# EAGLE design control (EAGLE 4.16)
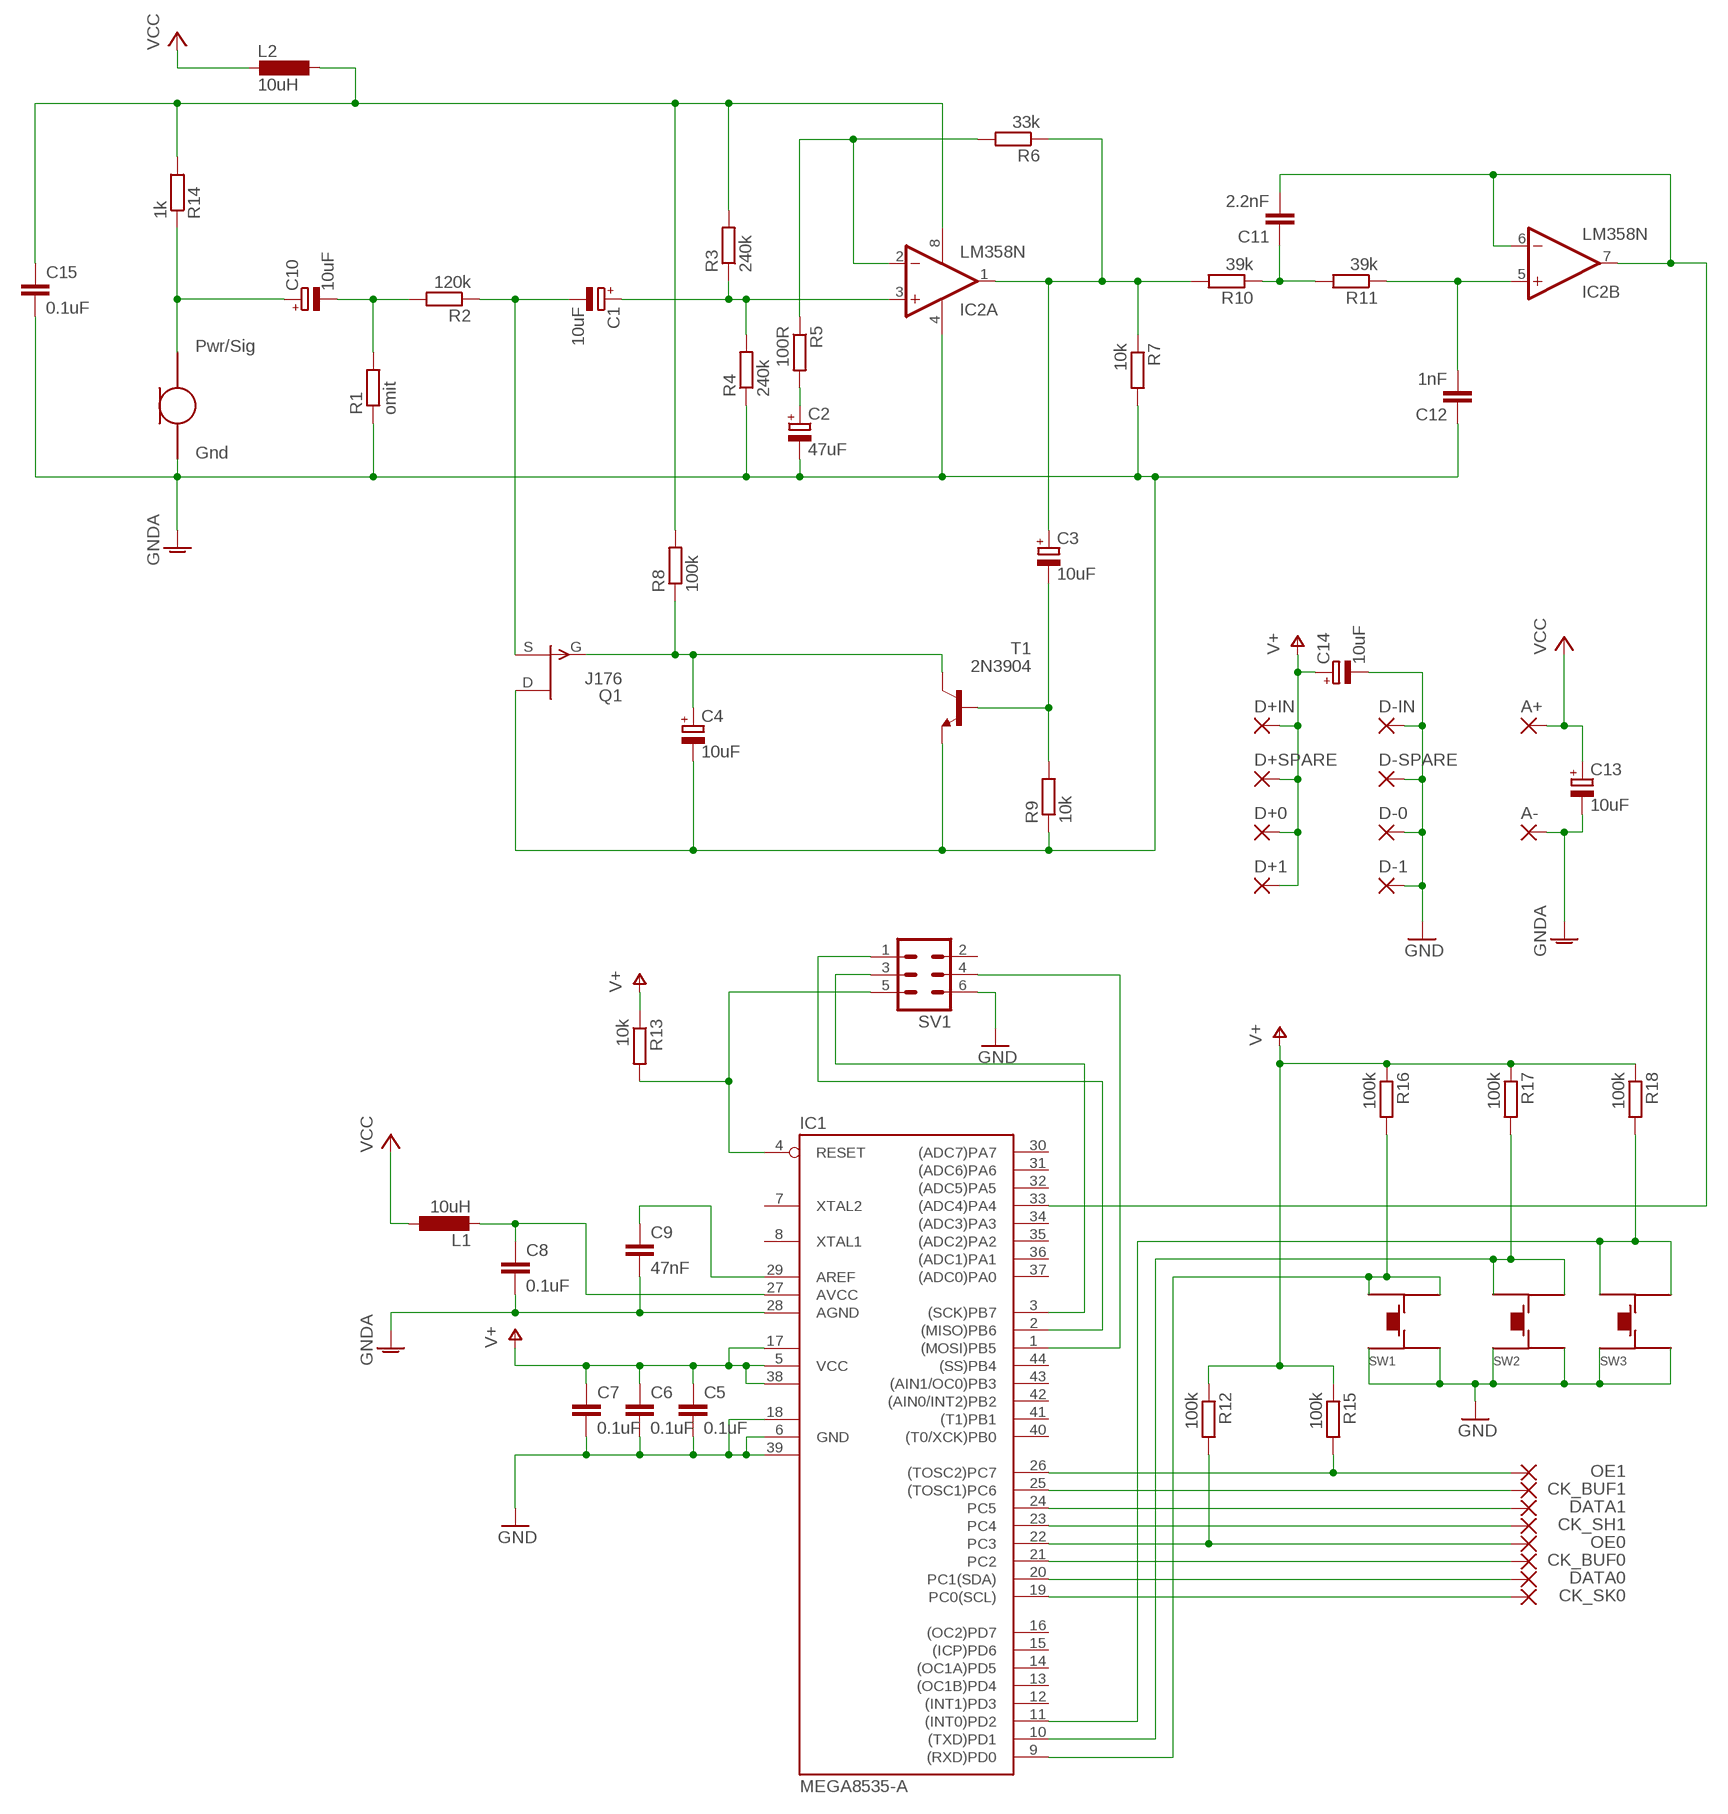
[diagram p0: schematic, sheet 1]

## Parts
A+  2,54/1,0  [2,54/1,0]
A-  2,54/1,0  [2,54/1,0]
C1  10uF  CPOL-EUA/3216-18W  [A/3216-18W]
C2  47uF  CPOL-EUE15-5AXIAL  [E15-5]
C3  10uF  CPOL-EUA/3216-18W  [A/3216-18W]
C4  10uF  CPOL-EUA/3216-18W  [A/3216-18W]
C5  0.1uF  C-EUC0805K  [C0805K]
C6  0.1uF  C-EUC0805K  [C0805K]
C7  0.1uF  C-EUC0805K  [C0805K]
C8  0.1uF  C-EUC0805  [C0805]
C9  47nF  C-EU050-024X044  [C050-024X044]
C10  10uF  CPOL-EUA/3216-18W  [A/3216-18W]
C11  2.2nF  C-EU050-024X044  [C050-024X044]
C12  1nF  C-EU050-024X044  [C050-024X044]
C13  10uF  CPOL-EUA/3216-18W  [A/3216-18W]
C14  10uF  CPOL-EUA/3216-18W  [A/3216-18W]
C15  0.1uF  C-EUC0805K  [C0805K]
CK_BUF0  2,54/1,0  [2,54/1,0]
CK_BUF1  2,54/1,0  [2,54/1,0]
CK_SH1  2,54/1,0  [2,54/1,0]
CK_SK0  2,54/1,0  [2,54/1,0]
D+0  2,54/1,0  [2,54/1,0]
D+1  2,54/1,0  [2,54/1,0]
D+IN  2,54/1,0  [2,54/1,0]
D+SPARE  2,54/1,0  [2,54/1,0]
D-0  2,54/1,0  [2,54/1,0]
D-1  2,54/1,0  [2,54/1,0]
D-IN  2,54/1,0  [2,54/1,0]
D-SPARE  2,54/1,0  [2,54/1,0]
DATA0  2,54/1,0  [2,54/1,0]
DATA1  2,54/1,0  [2,54/1,0]
IC1  MEGA8535-A  [TQFP44]
IC2  LM358N  [DIL08]
L1  10uH  L-EU0207/10  [0207/10]
L2  10uH  L-EU0207/10  [0207/10]
MIC1  ELECMIC  [MICPAC]
OE0  2,54/1,0  [2,54/1,0]
OE1  2,54/1,0  [2,54/1,0]
Q1  J176  [TO92-]
R1  omit  R-EU_0207/10  [0207/10]
R2  120k  R-EU_0207/10  [0207/10]
R3  240k  R-EU_0207/10  [0207/10]
R4  240k  R-EU_0207/10  [0207/10]
R5  100R  R-EU_0207/10  [0207/10]
R6  33k  R-EU_0207/10  [0207/10]
R7  10k  R-EU_0207/10  [0207/10]
R8  100k  R-EU_0207/10  [0207/10]
R9  10k  R-EU_0207/10  [0207/10]
R10  39k  R-EU_0207/10  [0207/10]
R11  39k  R-EU_0207/10  [0207/10]
R12  100k  R-EU_0207/10  [0207/10]
R13  10k  R-EU_0207/10  [0207/10]
R14  1k  R-EU_0207/10  [0207/10]
R15  100k  R-EU_0207/10  [0207/10]
R16  100k  R-EU_0207/10  [0207/10]
R17  100k  R-EU_0207/10  [0207/10]
R18  100k  R-EU_0207/10  [0207/10]
SV1  MA03-2  [MA03-2]
SW1  PUSHSW  [SWITCHMOMPAC]
SW2  PUSHSW  [SWITCHMOMPAC]
SW3  PUSHSW  [SWITCHMOMPAC]
T1  2N3904  2N3904TO92INLINE  [TO92-CBE]

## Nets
AMP+: C15.1 IC2.8(P:V+) L2.1 R3.2 R8.2 R14.2
GND: C5.2 C6.2 C7.2 C14.- D-0.1(P) D-1.1(P) D-IN.1(P) D-SPARE.1(P) IC1.6(GND) IC1.18(GND1) IC1.39(GND2) SV1.6 SW1.P$1 SW1.P$2 SW2.P$1 SW2.P$2 SW3.P$1 SW3.P$2
GNDA: A-.1(P) C2.- C4.- C8.2 C9.2 C12.1 C13.- C15.2 IC1.28(AGND) IC2.4(P:V-) MIC1.P$1(GND) Q1.3(D) R1.1 R4.1 R7.2 R9.1 T1.E
N$1: C8.1 IC1.27(AVCC) L1.2
N$2: IC1.3((SCK)PB7) SV1.3
N$3: C9.1 IC1.29(AREF)
N$4: IC1.2((MISO)PB6) SV1.1
N$5: IC1.4(RESET) R13.2 SV1.5
N$6: IC1.1((MOSI)PB5) SV1.4
N$7: C10.+ MIC1.P$2(PWRSIG) R14.1
N$8: C10.- R1.2 R2.2
N$9: C1.- Q1.1(S) R2.1
N$10: C1.+ IC2.3(A:+IN) R3.1 R4.2
N$12: C3.+ IC2.1(A:OUT) R6.1 R7.1 R10.2
N$13: IC2.2(A:-IN) R5.1 R6.2
N$14: C2.+ R5.2
N$15: C4.+ Q1.2(G) R8.1 T1.C
N$17: C11.2 IC1.33((ADC4)PA4) IC2.6(B:-IN) IC2.7(B:OUT)
N$18: C3.- R9.2 T1.B
N$19: C11.1 R10.1 R11.2
N$20: IC1.22(PC3) OE0.1(P) R12.2
N$21: C12.2 IC2.5(B:+IN) R11.1
N$22: CK_SH1.1(P) IC1.23(PC4)
N$23: CK_SK0.1(P) IC1.19(PC0(SCL))
N$24: DATA0.1(P) IC1.20(PC1(SDA))
N$25: CK_BUF0.1(P) IC1.21(PC2)
N$26: DATA1.1(P) IC1.24(PC5)
N$27: CK_BUF1.1(P) IC1.25((TOSC1)PC6)
N$28: IC1.26((TOSC2)PC7) OE1.1(P) R15.2
N$29: IC1.9((RXD)PD0) R16.2 SW1.P$3 SW1.P$4
N$30: IC1.10((TXD)PD1) R17.2 SW2.P$3 SW2.P$4
N$31: IC1.11((INT0)PD2) R18.2 SW3.P$3 SW3.P$4
V+: C5.1 C6.1 C7.1 C14.+ D+0.1(P) D+1.1(P) D+IN.1(P) D+SPARE.1(P) IC1.5(VCC) IC1.17(VCC1) IC1.38(VCC2) R12.1 R13.1 R15.1 R16.1 R17.1 R18.1
VCC: A+.1(P) C13.+ L1.1 L2.2
Unconnected: IC1.7(XTAL2) IC1.8(XTAL1) IC1.12((INT1)PD3) IC1.13((OC1B)PD4) IC1.14((OC1A)PD5) IC1.15((ICP)PD6) IC1.16((OC2)PD7) IC1.30((ADC7)PA7) IC1.31((ADC6)PA6) IC1.32((ADC5)PA5) IC1.34((ADC3)PA3) IC1.35((ADC2)PA2) IC1.36((ADC1)PA1) IC1.37((ADC0)PA0) IC1.40((T0/XCK)PB0) IC1.41((T1)PB1) IC1.42((AIN0/INT2)PB2) IC1.43((AIN1/OC0)PB3) IC1.44((SS)PB4) SV1.2

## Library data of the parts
A+ A- CK_BUF0 CK_BUF1 CK_SH1 CK_SK0 D+0 D+1 D+IN D+SPARE D-0 D-1 D-IN D-SPARE DATA0 DATA1 OE0 OE1 = wirepad:2,54/1,0: THROUGH-HOLE PAD
C1-C4 C10 C13 C14 = rcl:CPOL-EU: POLARIZED CAPACITOR, European symbol
C5-C9 C11 C12 C15 = rcl:C-EU: CAPACITOR, European symbol
IC1 = atmel:MEGA8535: MICROCONTROLLER 8 Kbytes FLASH 512 bytes SRAM 512 bytes EEPROM USART 8-channel 10 bit ADC Source: avr.lbr
IC2 = linear:LM358: OP AMP
L1 L2 = rcl:L-EU: INDUCTOR, European symbol
MIC1 = iain:ELECMIC: Elect Mic
Q1 = iain:J176: P-Channel Junction FET Swap : Drain - Source / correct Symbol 2005.08.09 | librarian@cadsoft.de
R1-R18 = rcl:R-EU_: RESISTOR, European symbol
SV1 = con-lstb:MA03-2: PIN HEADER
SW1-SW3 = iain:PUSHSW
T1 = transistor:2N3904: NPN TRANSISTOR

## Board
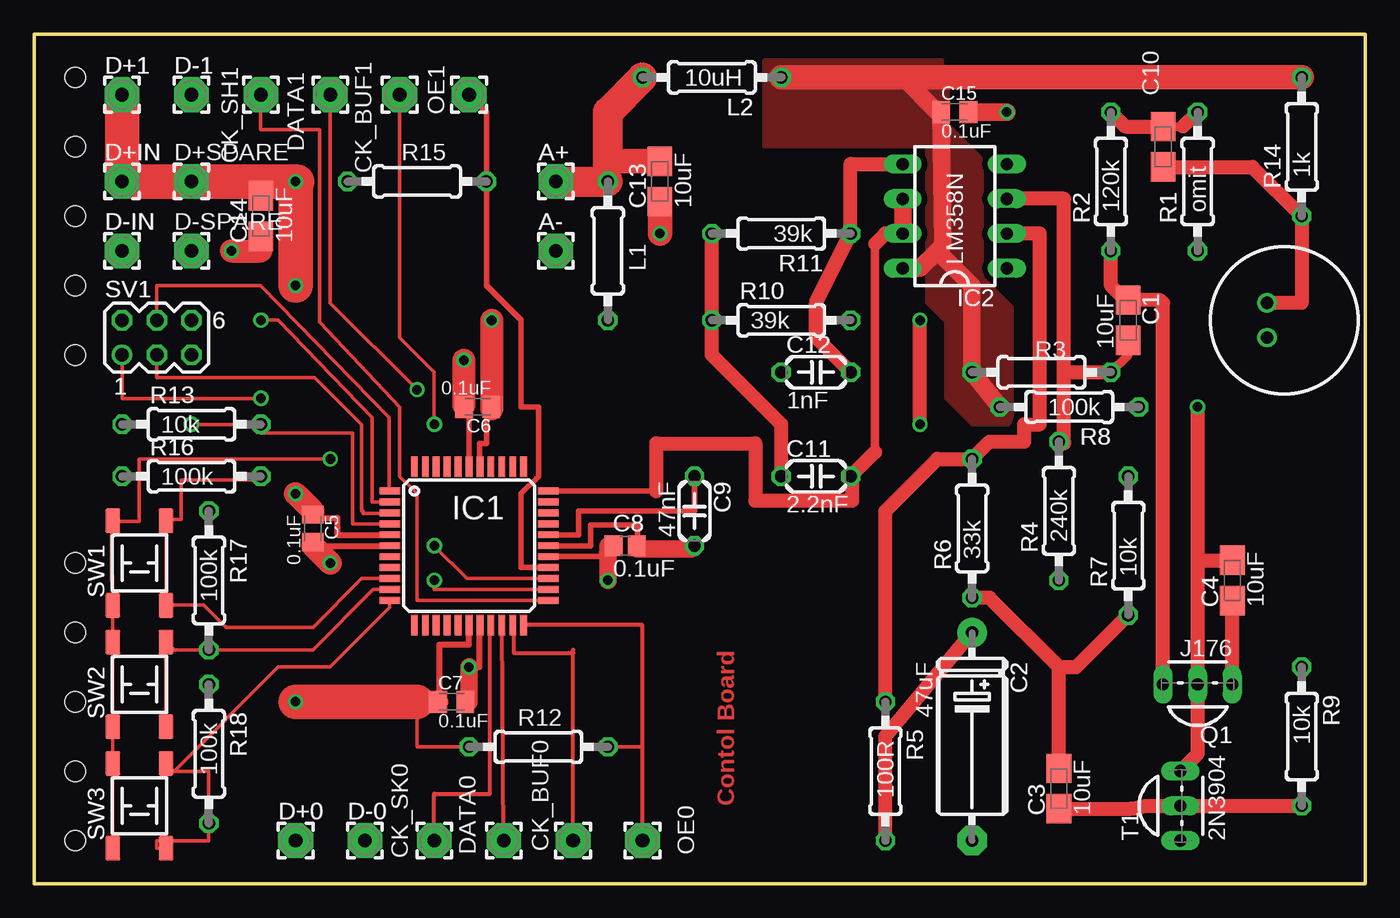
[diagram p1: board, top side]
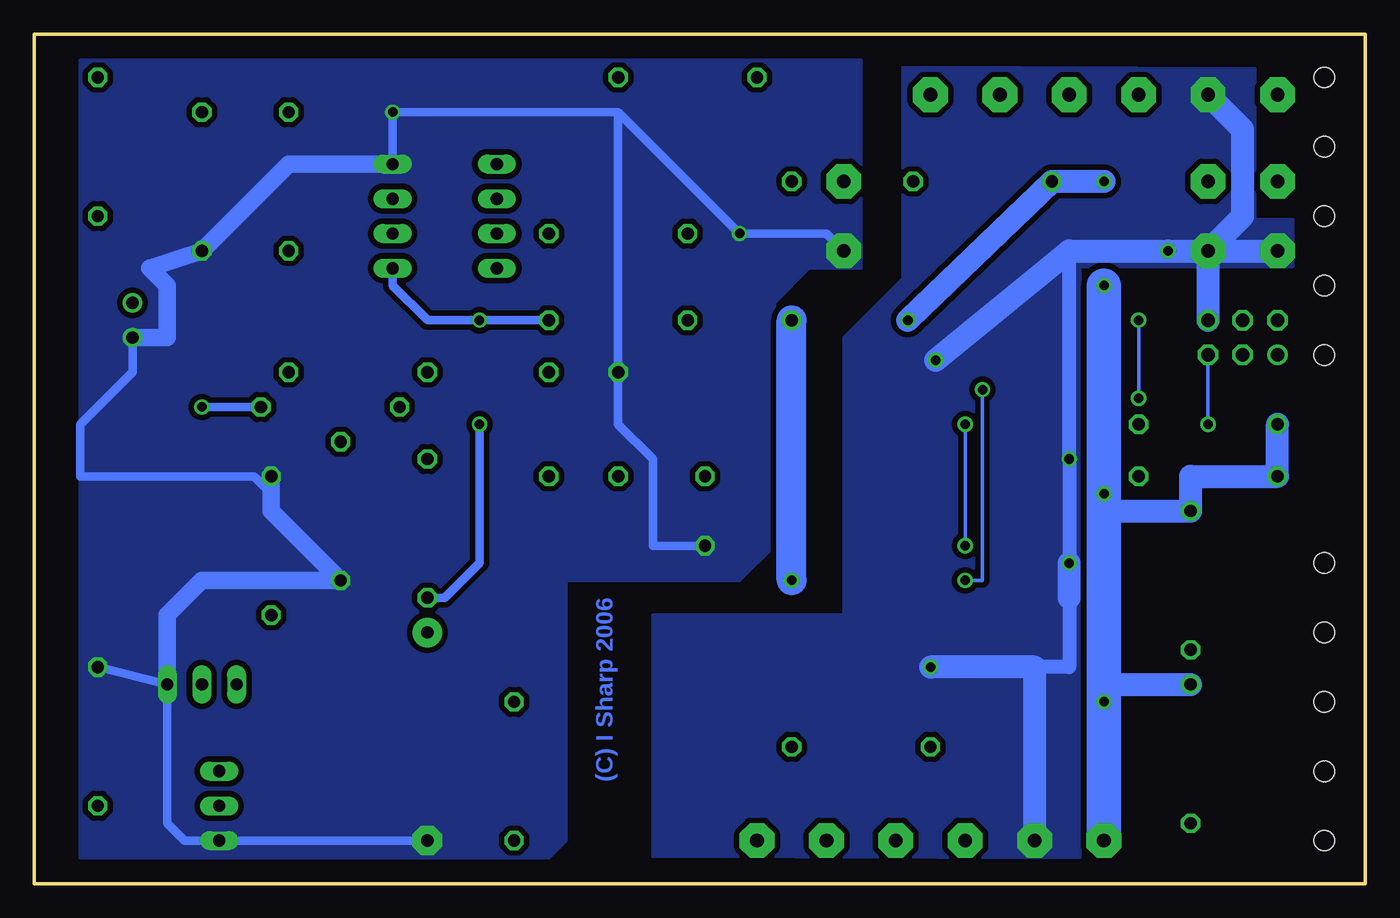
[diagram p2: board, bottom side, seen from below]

Size 97.46 x 62.22 mm. Coordinates in mm from the lower left corner, seen from the top.
Outline: 0,0 97.46,0 97.46,62.22 0,62.22 0,0
Copper layers (1*16): Top 0.035mm / dielectric 1.5mm / Bottom 0.035mm
Design rules "10mils with 0.7mm min drill": minimum track width 10mil, minimum drill 0.7mm, track to track 10mil, track to pad 10mil, pad to pad 10mil, via to via 10mil, smd to smd 10mil, copper to edge 40mil, drill to drill 10mil, minimum pad ring 10mil, minimum via ring 8mil, stop-mask expansion 0mil, vias tented up to drill 0mil, thermal gap 10mil
Holes 1.5 mm at 3.01,59.05 3.01,53.97 3.01,48.89 3.01,43.81 3.01,38.73 3.01,3.17 3.01,8.25 3.01,13.33 3.01,18.41 3.01,23.49

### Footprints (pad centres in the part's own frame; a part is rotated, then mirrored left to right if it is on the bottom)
2,54/1,0 = drill 1 pad 2.54 octagon: 1 0,0
A/3216-18W = smd 2.15 x 1.8: + 1.475,0; - -1.475,0
E15-5 = drill 0.9 pad 2.159 round: + -7.62,0 | drill 0.9 pad 2.159 octagon: - 7.62,0
C0805K = smd 1.3 x 1.6: 1 -1,0; 2 1,0
C0805 = smd 1.3 x 1.5: 1 -0.85,0; 2 0.85,0
C050-024X044 = drill 0.9 octagon: 1 -2.54,0; 2 2.54,0
TQFP44 = smd 1.5 x 0.5: 1 -5.8,4; 2 -5.8,3.2; 3 -5.8,2.4; 4 -5.8,1.6; 5 -5.8,0.8; 6 -5.8,0; 7 -5.8,-0.8; 8 -5.8,-1.6; 9 -5.8,-2.4; 10 -5.8,-3.2; 11 -5.8,-4; 23 5.8,-4; 24 5.8,-3.2; 25 5.8,-2.4; 26 5.8,-1.6; 27 5.8,-0.8; 28 5.8,0; 29 5.8,0.8; 30 5.8,1.6; 31 5.8,2.4; 32 5.8,3.2; 33 5.8,4 | smd 0.5 x 1.5: 12 -4,-5.8; 13 -3.2,-5.8; 14 -2.4,-5.8; 15 -1.6,-5.8; 16 -0.8,-5.8; 17 0,-5.8; 18 0.8,-5.8; 19 1.6,-5.8; 20 2.4,-5.8; 21 3.2,-5.8; 22 4,-5.8; 34 4,5.8; 35 3.2,5.8; 36 2.4,5.8; 37 1.6,5.8; 38 0.8,5.8; 39 0,5.8; 40 -0.8,5.8; 41 -1.6,5.8; 42 -2.4,5.8; 43 -3.2,5.8; 44 -4,5.8
DIL08 = drill 0.9 long: 1 -3.81,-3.81; 2 -1.27,-3.81; 3 1.27,-3.81; 4 3.81,-3.81; 5 3.81,3.81; 6 1.27,3.81; 7 -1.27,3.81; 8 -3.81,3.81
0207/10 = drill 0.9 octagon: 1 -5.08,0; 2 5.08,0
MICPAC = drill 0.9 round: P$1 1.27,1.27; P$2 1.27,-1.27
TO92- = drill 0.9 long: 1 2.54,0; 2 0,0; 3 -2.54,0
MA03-2 = drill 1 round: 1 -2.54,-1.27 | drill 1 octagon: 2 -2.54,1.27; 3 0,-1.27; 4 0,1.27; 5 2.54,-1.27; 6 2.54,1.27
SWITCHMOMPAC = smd 1.8 x 1.1: P$1 3.1,1.95; P$2 -3.1,1.95; P$3 -3.1,-1.95; P$4 3.1,-1.95
TO92-CBE = drill 0.9 long: B 0,0; C 2.54,0; E -2.54,0

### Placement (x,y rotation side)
A+  38.19,51.43 0 top
A-  38.19,46.35 0 top
C1  80.1,41.27 270 top
C2  68.67,10.79 270 top
C3  75.02,6.98 90 top
C4  87.72,22.22 90 top
C5  20.41,26.03 270 top
C6  32.47,34.92 180 top
C7  30.57,13.33 0 top
C8  43.27,24.76 0 top
C9  48.35,27.3 270 top
C10  82.64,53.97 270 top
C11  57.24,29.84 0 top
C12  57.24,37.46 0 top
C13  45.81,51.43 90 top
C14  16.6,48.89 90 top
C15  67.4,56.51 0 top
CK_BUF0  39.46,3.17 0 top
CK_BUF1  26.76,57.78 0 top
CK_SH1  16.6,57.78 0 top
CK_SK0  29.3,3.17 0 top
D+0  19.14,3.17 0 top
D+1  6.44,57.78 0 top
D+IN  6.44,51.43 0 top
D+SPARE  11.52,51.43 0 top
D-0  24.22,3.17 0 top
D-1  11.52,57.78 0 top
D-IN  6.44,46.35 0 top
D-SPARE  11.52,46.35 0 top
DATA0  34.38,3.17 0 top
DATA1  21.68,57.78 0 top
IC1  31.84,24.76 0 top
IC2  67.4,48.89 90 top
L1  42,46.35 270 top
L2  49.62,59.05 180 top
MIC1  91.53,41.27 180 top
OE0  44.54,3.17 0 top
OE1  31.84,57.78 0 top
Q1  85.18,14.6 180 top
R1  85.18,51.43 90 top
R2  78.83,51.43 90 top
R3  73.75,37.46 180 top
R4  75.02,27.3 90 top
R5  62.32,8.25 270 top
R6  68.67,26.03 90 top
R7  80.1,24.76 90 top
R8  75.78,34.92 180 top
R9  92.8,10.79 270 top
R10  54.7,41.27 0 top
R11  54.7,47.62 180 top
R12  36.92,10.03 0 top
R13  11.52,33.65 0 top
R14  92.8,53.97 90 top
R15  28.03,51.43 0 top
R16  11.52,29.84 0 top
R17  12.79,22.22 270 top
R18  12.79,9.52 270 top
SV1  8.98,40 0 top
SW1  7.71,23.49 90 top
SW2  7.71,14.6 90 top
SW3  7.71,5.71 90 top
T1  83.91,5.71 90 top

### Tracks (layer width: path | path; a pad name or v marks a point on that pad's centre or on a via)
AMP+
  Top 1.27: 63.59,59.05 66.13,56.51 C15.1 66.55,46.77 66.13,46.35 | 66.13,46.35 64.86,45.08 IC2.8 | 66.13,46.35 68.67,43.81 R3.2 R8.2
  Top 1.778: L2.1 63.59,59.05 R14.2
  pour Top (isolate 0.406, no thermals): 53.43,60.32 53.43,53.97 65.24,53.97 65.37,53.84 65.37,42.54 66.76,41.14 66.76,35.55 68.67,33.65 71.34,33.65 71.59,33.9 71.59,42.29 69.43,44.45 69.43,53.08 66.89,55.62 66.89,58.92 66.51,59.3 66.51,60.32
GND  (via drill 0.7)
  Top 0.254: 5.8,26.54 SW1.P$1 | 5.68,22.6 5.68,22.22 | 5.68,22.6 5.68,26.41 5.8,26.54 | 5.68,22.6 5.76,22.52 SW1.P$2 5.76,17.86 5.68,17.77 SW2.P$1 5.76,11.72 5.8,11.68 5.76,11.63 SW2.P$2 SW3.P$1 | SW3.P$1 5.76,8.71 5.68,8.63 | SW3.P$2 5.93,2.79 5.76,2.96 SW3.P$1 | 5.8,26.54 7.71,26.54 7.71,31.11 v21.68,31.11
  Top 0.406: 31.84,30.35 IC1.39 31.84,34.92 C6.2
  Top 0.457: 20.41,24.76 IC1.6 | v31.84,15.87 32.6,15.87 32.6,18.96 IC1.18
  Top 1.016: 20.41,24.76 C5.2 | 31.84,13.33 C7.2 | 16.6,46.35 C14.- | 31.46,35.05 31.58,34.92 C6.2
  Top 1.27: v31.84,15.87 31.84,13.33
  Top 1.676: v21.68,23.49 20.41,24.76 | v14.44,46.35 16.6,46.35 | v31.46,38.35 31.46,35.05
  Bottom 1.016: 21.68,46.35 v21.68,31.11 21.68,20.95 21.68,15.87 24.22,15.87
  Bottom 1.676: D-SPARE.1 D-IN.1 | D-SPARE.1 v14.44,46.35 21.68,46.35 v31.46,38.35 | 21.68,20.95 v21.68,23.49 | v31.84,15.87 24.22,15.87 D-0.1 | D-SPARE.1 SV1.6 | D-SPARE.1 8.98,48.89 8.98,55.24 D-1.1
  pour Bottom (isolate 0.406, no thermals): 5.3,45.21 5.3,48.64 8.09,48.64 8.09,59.69 33.87,59.81 33.87,44.32 38.19,40 38.19,19.68 52.16,19.68 52.16,2.03 20.92,1.9 20.92,45.21
GNDA  (via drill 0.7)
  Top 0.406: IC1.28 40.73,24.76 40.73,26.28 44.03,26.28 44.16,26.16 44.16,24.51 44.12,24.54 C8.2
  Top 0.61: 48.1,24.51 C9.2
  Top 1.016: Q1.3 C4.-
  Top 1.27: 44.16,24.51 48.1,24.51 | v71.21,56.51 C15.2
  Top 1.778: v45.81,47.62 C13.-
  Bottom 0.61: 54.7,56.51 C12.1 54.7,33.65 52.16,31.11 52.16,24.76 C9.2 | 54.7,56.51 v71.21,56.51 IC2.4 | A-.1 39.46,47.62 v45.81,47.62 54.7,56.51 | R9.1 Q1.3 87.72,4.44 86.45,3.17 T1.E C2.- | MIC1.P$1 90.26,37.46 94.07,33.65 94.07,29.84 81.37,29.84 80.1,28.57
  Bottom 1.27: IC2.4 78.83,52.7 R1.1 88.99,45.08 87.72,43.81 87.72,40 MIC1.P$1 | R7.2 80.1,28.57 80.1,27.3 R4.1 85.18,22.22 87.72,19.68 Q1.3
  pour Bottom (isolate 0.406, no thermals): 36.92,60.32 36.92,45.08 40.73,45.08 43.27,42.54 43.27,24.76 45.81,22.22 58.51,22.22 58.51,3.17 59.78,1.9 94.07,1.9 94.07,60.32
N$1  (via drill 0.7)
  Top 0.406: IC1.27 41.53,23.96 41.53,24.29 42,24.76
  Top 1.016: 42,24.76 C8.1
  Top 1.27: 42,24.76 v42,22.22
  Bottom 2.184: v42,22.22 L1.2
N$2
  Top 0.254: 26.04,27.13 26.12,27.05 26.38,27.3 | 26.04,27.13 IC1.3 | 26.04,27.13 24.09,27.13 24.09,27.3 23.96,27.3 23.96,33.65 20.54,37.08 8.98,37.08 SV1.3
N$3
  Top 0.406: IC1.29 39.84,25.56 39.84,27.3 48.35,27.3 C9.1
N$4  (via drill 0.7)
  Top 0.254: IC1.2 24.73,27.96 24.73,34.16 17.87,41.27 v16.6,41.27 | v16.6,35.55 6.44,35.55 SV1.1
  Bottom 0.254: v16.6,35.55 v16.6,41.27
N$5  (via drill 0.7)
  Top 0.254: IC1.4 23.33,26.36 23.33,33.02 16.6,33.02 R13.2 v11.52,33.65
  Bottom 0.254: v11.52,33.65 SV1.5
N$6
  Top 0.254: SV1.4 8.98,43.81 16.6,43.81 26,34.16 26,28.7 26.04,28.74 IC1.1
N$7
  Top 1.016: C10.+ 89.19,52.49 R14.1 92.8,42.54 MIC1.P$2
N$8
  Top 0.61: C10.- 84.11,55.45
  Top 1.016: C10.- 79.89,55.45 R2.2 | 84.11,55.45 R1.2
N$9
  Top 0.61: C1.- 80.1,42.54 | 82.64,42.54 82.43,42.74
  Top 1.016: R2.1 78.83,43.81 80.1,42.54 | 82.43,42.74 C1.- | Q1.1 82.64,42.54
N$10
  Top 0.61: C1.+ 80.1,38.73 R3.1
  Top 1.016: IC2.3 75.4,50.16 75.4,37.46 | 75.4,37.46 R3.1 | R4.2 75.4,32.38 | 75.4,32.38 75.4,32.25 | 75.4,32.38 75.4,37.46
N$12  (via drill 0.7)
  Top 1.016: C3.+ 75.02,15.87 | R6.1 69.94,20.95 75.02,15.87 | 75.02,15.87 76.29,15.87 R7.1 | v64.86,33.65 v64.86,41.27
  Bottom 0.61: R6.1 67.4,20.95 64.86,23.49 v64.86,33.65 | IC2.1 71.21,43.81 68.67,41.27 v64.86,41.27 R10.2
N$13
  Top 1.016: IC2.2 73.62,47.62 73.62,33.65 72.48,33.65 72.48,32.38 69.94,32.38 R6.2 66.13,31.11 62.32,27.3 R5.1
N$14
  Top 1.016: R5.2 62.32,10.79 C2.+
N$15  (via drill 0.7)
  Top 0.61: 85.18,23.49 85.38,23.7
  Top 1.016: T1.C 85.18,9.52 Q1.2 85.18,23.49 v85.18,34.92 | 85.38,23.7 C4.+
  Bottom 0.61: v85.18,34.92 R8.1
N$17
  Top 0.406: IC1.33 45.55,28.76 | 59.91,29.84 C11.2
  Top 0.61: 61.56,31.62 61.56,46.86
  Top 1.016: 45.55,28.76 45.55,32.25 52.79,32.25 52.79,28.06 59.91,28.06 59.91,29.84 | IC2.7 62.32,47.62 61.56,46.86 | C11.2 61.56,31.62
  Top 1.27: IC2.7 IC2.6
N$18
  Top 1.016: C3.- 80.3,5.5 81.37,5.71 T1.B R9.2
N$19
  Top 1.016: C11.1 54.7,33.65 49.62,38.73 R10.1 R11.2
N$20
  Top 0.254: 44.54,10.03 R12.2
  Top 0.305: IC1.22 44.54,18.96 44.54,10.03 OE0.1
N$21
  Top 1.016: IC2.5 59.78,52.7 R11.1 57.24,42.54 57.24,40 C12.2
N$22
  Top 0.254: IC1.23 28.03,20.76 28.03,28.57 26.76,29.84 26.76,34.92 20.92,41.14 20.92,55.24 16.6,55.24 CK_SH1.1
N$23
  Top 0.305: IC1.19 33.36,18.96 33.36,6.6 29.3,6.6 CK_SK0.1
N$24
  Top 0.305: IC1.20 34.25,18.96 DATA0.1
N$25
  Top 0.305: IC1.21 35.14,18.96 35.14,16.89 39.46,16.89 | 39.46,16.89 39.46,17.14 | CK_BUF0.1 39.46,16.89
N$26  (via drill 0.7)
  Top 0.254: IC1.24 29.3,21.56 v29.3,22.22 | v28.03,36.19 21.68,42.54 DATA1.1
  Bottom 0.254: v29.3,22.22 28.03,22.22 v28.03,36.19
N$27  (via drill 0.7)
  Top 0.254: IC1.25 31.7,22.36 v29.3,24.76 | v29.3,33.65 29.3,37.46 26.76,40 CK_BUF1.1
  Bottom 0.254: v29.3,24.76 v29.3,33.65
N$28
  Top 0.406: IC1.26 35.65,23.16 35.65,28.57 36.92,29.84 36.92,34.92 35.65,34.92 35.65,41.27 33.11,43.81 R15.2 33.11,56.51 OE1.1
N$29
  Top 0.254: IC1.9 23.98,22.36 20.41,18.79 14.06,18.79 12.41,20.44 9.74,20.44 9.69,20.39 SW1.P$3 SW1.P$4 | SW1.P$4 9.74,26.66 10.76,26.66 10.76,29.59 16.6,29.59 R16.2 | SW1.P$4
N$30
  Top 0.254: IC1.10 24.83,21.56 20.41,17.14 R17.2 10.25,17.14 | SW2.P$3 9.66,11.47 9.61,11.42 | 9.74,11.42 SW2.P$3 | SW2.P$4 9.69,17.7 10.25,17.14 | 10.25,17.14 9.61,17.14 9.61,11.68 9.74,11.55 9.69,11.5 SW2.P$3
N$31
  Top 0.254: SW3.P$3 8.98,2.61 8.98,3.17 12.79,3.17 R18.2 12.79,8.25 10.25,8.25 | 10.25,8.25 SW3.P$4 | IC1.11 26.04,20.23 21.68,15.87 17.87,15.87 10.25,8.25
V+  (via drill 0.7)
  Top 0.254: 28.03,13.33 28.03,10.03 R12.1
  Top 0.406: C5.1 20.41,26.79 | 32.6,30.56 32.6,30.35 | 32.6,30.56 IC1.38 | 32.6,30.56 32.6,32.25 33.11,32.25 33.11,34.92 C6.1
  Top 0.457: IC1.5 22.19,25.56 22.19,26.79 20.41,26.79 | IC1.17 31.84,17.52 29.68,17.52 29.68,13.33
  Top 1.016: 33.49,34.79 C6.1 | 20.41,27.3 C5.1 | 19.27,51.43 C14.+
  Top 1.27: 29.68,13.33 C7.1 28.03,13.33
  Top 1.676: v33.49,41.27 33.49,34.79 | v19.14,28.57 20.41,27.3
  Top 2.54: v19.14,43.81 v19.14,51.43 19.27,51.43 D+SPARE.1 D+IN.1 D+1.1 | v19.14,13.33 28.03,13.33
  Bottom 1.676: R13.1 R16.1 12.79,29.84 R17.1 19.14,27.3 | v33.49,41.27 R15.1 v19.14,51.43 | 19.14,14.6 R18.1
  Bottom 2.54: v19.14,43.81 v19.14,28.57 19.14,27.3 19.14,14.6 v19.14,13.33 D+0.1
VCC
  Top 1.016: L1.1 42,52.7 42.2,52.91
  Top 1.778: 42.2,52.91 C13.+
  Top 2.184: A+.1 L1.1 | 42,52.7 42,56.51 L2.2

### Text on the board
Top: Contol Board
Bottom: (C) I Sharp 2006
tNames: D+1 | D-1 | 10uH | L2 | C15 | 0.1uF | D+IN | A+ | R14 | 1k | C13 | 10uF | 120k | omit | D-IN | A- | 39k | R2 | R1 | C14 | 10uF | R11 | LM358N | SV1 | IC2 | 10uF | C1 | R10 | 6 | 39k | C12 | 0.1uF | 1 | R13 | 100k | C6 | 1nF | 10k | R8 | R16 | C11 | 100k | 47nF | C9 | 0.1uF | C5 | 2.2nF | R17 | C8 | 240k | 100k | R4 | R6 | 33k | 0.1uF | 10k | SW1 | R7 | C4 | 10uF | J176 | 47uF | C2 | C7 | 10k | R9 | SW2 | R18 | 100k | 0.1uF | R5 | Q1 | 100R | C3 | 10uF | D+0 | D-0 | SW3 | T1 | 2N3904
